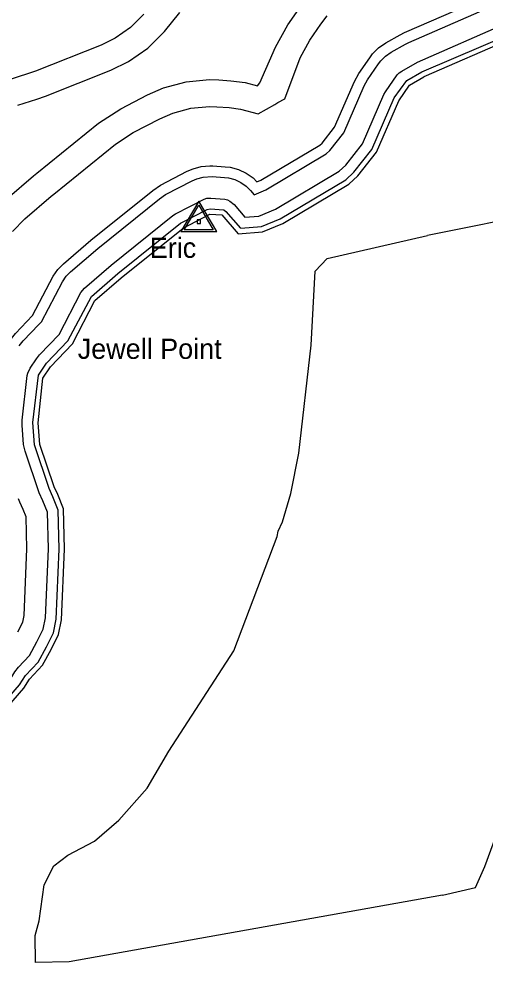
# Model space of a CAD drawing. Extents: x 2532689 to 2764727, y 536648 to 732970.
# Drawn here: x 2668083 to 2671553, y 577202 to 584335 of the extents above; entities that cross this region are included whole.
import ezdxf

# ---------------------------------------------------------------- set-up
doc = ezdxf.new("R2010")
doc.units = 0
for name, color, linetype in [('Exist Hydrographic Buffer Line', 7, 'Continuous'), ('Exist Hydrographic Creek Double Shore', 7, 'Continuous'), ('Exist Hydrographic Creek Single Shore', 7, 'Continuous'), ('Exist Hydrographic Point Label', 7, 'Continuous'), ('Exist Survey Geodetic Marker CELL', 7, 'Continuous'), ('Exist Survey Geodetic Marker Label', 7, 'Continuous')]:
    doc.layers.add(name, color=color, linetype=linetype)

msp = doc.modelspace()

# ---------------------------------------------------------------- linework, layer by layer
at = {"layer": 'Exist Hydrographic Buffer Line'}
for points in [[(2669075.8, 583062.5), (2669135.1, 583101.4), (2669333.4, 583204.6), (2669376.2, 583223.6), (2669437.1, 583239.8), (2669499.7, 583245.4), (2669523.9, 583244.6), (2669614.9, 583238.4), (2669653, 583233.7), (2669713.7, 583217.5), (2669770.5, 583191), (2669822, 583155), (2669851.5, 583125.8), (2669881.1, 583138.1), (2670318.4, 583397.5), (2670335.3, 583413.4), (2670427.9, 583531.7), (2670575.6, 583870.7), (2670608.6, 583930.4), (2670689.6, 584048.6), (2670710.9, 584076.5), (2670755, 584120.8), (2670809.3, 584158.4), (2670916.4, 584219), (2670949.4, 584235.5), (2671609.2, 584524.3)], [(2670674.6, 583885.2), (2670755.6, 584003.4), (2670772, 584025.1), (2670806.7, 584059.6), (2670848.5, 584088.8), (2670955.5, 584149.4), (2670981.4, 584162.2), (2671657.8, 584457.6)], [(2669009.2, 584372.1), (2668910.8, 584273.6), (2668796.5, 584193.6), (2668691.6, 584142.8), (2668203.5, 583949.1), (2668153.1, 583930.9), (2667984.5, 583876.8), (2667818.4, 583762.5), (2667764.5, 583728.3), (2667638, 583669.4), (2667519.1, 583637.4), (2667481.1, 583491.4), (2667422.3, 583365.1), (2667342.3, 583250.8), (2667301.5, 583210), (2667309.3, 583102.1), (2667311.6, 583043.8), (2667299.3, 582904.9), (2667259.3, 582759.1), (2667212.3, 582635.7)], [(2667994, 583001.2), (2668190, 583170), (2668215, 583191), (2668673.9, 583560.8), (2668839.2, 583669), (2669037.3, 583772.2), (2669157.4, 583825), (2669325.8, 583870.2), (2669499.5, 583885.3), (2669566.7, 583883.1), (2669657.8, 583877), (2669764.4, 583864.1), (2669854.4, 583839.9), (2669873.5, 583862), (2669988.7, 584126.3), (2670080.8, 584292.2), (2670161.8, 584410.4)], [(2668033.7, 582757.7), (2668124.6, 582849.7), (2668320.6, 583018.5), (2668340.5, 583035.3), (2668799.6, 583405.1), (2668931.9, 583491.6), (2669129.8, 583594.8), (2669226.1, 583637.1), (2669360.6, 583673.2), (2669499.5, 583685.4), (2669553.4, 583683.5), (2669644.2, 583677.4), (2669729.5, 583667.1), (2669860.1, 583632.1), (2669983.6, 583701.7), (2670007.6, 583715.3), (2670057.4, 583743.2), (2670172, 584046.5), (2670245.6, 584179.1), (2670326.6, 584297.3), (2670373.8, 584359.3)], [(2668073.5, 583695.4), (2668214, 583740.5), (2668277.6, 583763.2), (2668765.6, 583957), (2668896.6, 584020.4), (2669039.3, 584120.3), (2669162.6, 584243.6), (2669277, 584384.1)], [(2669762.1, 582863.9), (2669865.3, 582871.7), (2669988.9, 582922.9), (2670463.2, 583204.4), (2670512.8, 583250.8), (2670635.7, 583407.8), (2670795.6, 583774.8), (2670806.7, 583794.7), (2670894.6, 583922.2), (2670909.4, 583937), (2670927.6, 583949.5), (2671045.6, 584015.6), (2671712.6, 584307.3)], [(2669731.9, 582781.3), (2669884.1, 582792.9), (2670024.6, 582851.3), (2670511.4, 583140), (2670572.1, 583196.6), (2670705, 583366.5), (2670872.7, 583749.6), (2670966.8, 583879.9), (2671077.5, 583942.3), (2671756.1, 584234.5)], [(2670394.3, 583359.2), (2670497, 583490.4), (2670648.8, 583838.7), (2670674.6, 583885.2)], [(2668228.2, 582064.8), (2668248.6, 582086.2), (2668404.1, 582383.5), (2668432, 582423.5), (2668463.7, 582455.7), (2668666.7, 582630.4), (2669125.9, 583000.2), (2669172, 583030.5), (2669370.1, 583133.7), (2669403.9, 583148.5), (2669451.1, 583161.1), (2669518.3, 583164.7), (2669609.4, 583158.6), (2669639.1, 583155), (2669686.3, 583142.3), (2669730.6, 583121.7), (2669770.5, 583093.7), (2669802.7, 583061.8), (2669829.8, 583030.3), (2669916.7, 583066.4), (2670366.6, 583333.1), (2670394.3, 583359.2)], [(2667895.7, 581056.9), (2667877.5, 581146.1), (2667865.6, 581306.5), (2667866.6, 581371), (2667901.5, 581704.1), (2667905, 581728.9), (2667921.4, 581789.6), (2667947.8, 581846.4), (2667959.5, 581865.6), (2668015.5, 581949.9), (2668055.1, 581999.3), (2668183, 582133.2), (2668334.8, 582423.5), (2668370.9, 582474.9), (2668411.5, 582516.3), (2668616.7, 582692.6), (2669075.8, 583062.5)], [(2668380.1, 581992), (2668542.5, 582303.5), (2668568.3, 582334.4), (2668767.2, 582505.8), (2669226.3, 582875.6), (2669246, 582888.6), (2669458.7, 582998.1), (2669478.7, 583003.5), (2669507.7, 583005.1), (2669611.4, 582997.4), (2669631.5, 582992), (2669650.6, 582983.2), (2669681.5, 582957.4), (2669762.1, 582863.9)], [(2668305.9, 580845.9), (2668196.6, 581170), (2668184.9, 581337.6), (2668226.3, 581688.6), (2668286.6, 581778.4), (2668445.9, 581945), (2668620.6, 582273.8), (2668817.5, 582443.5), (2669283.1, 582817.6), (2669481, 582920.8), (2669502.3, 582925.3), (2669604.2, 582916.8), (2669620.9, 582905.3), (2669727.9, 582781)], [(2668082.3, 581905.7), (2668113.1, 581944.1), (2668228.2, 582064.8)], [(2668232.4, 580813.7), (2668126.3, 581124.9), (2668116.1, 581174.3), (2668105.5, 581317.4), (2668106, 581353.1), (2668141.5, 581685.2), (2668146.8, 581704.5), (2668165.1, 581740.8), (2668211.7, 581811.2), (2668233.7, 581838.6), (2668380.1, 581992)], [(2666818.4, 577463.7), (2666823.5, 577816), (2666825.9, 577840.9), (2666831.3, 577860.6), (2666846, 577891.2), (2666965.4, 578084.7), (2667059.7, 578310.9), (2667093.5, 578365), (2668021.2, 579433), (2668050.9, 579483.1), (2668078.3, 579519), (2668159.2, 579603.7), (2668214.3, 579705.5), (2668262.1, 579799.6), (2668279.3, 579883.8), (2668300.5, 580396.8), (2668294.2, 580669.1), (2668259.4, 580753.4), (2668232.4, 580813.7)], [(2667052.8, 577186.2), (2666929.3, 577446.9), (2666900.6, 577604.7), (2666903.5, 577821.5), (2666909.7, 577842), (2667036.8, 578048.1), (2667145.3, 578303.1), (2668086, 579385.8), (2668129.5, 579457.3), (2668224, 579555.9), (2668285.1, 579668.2), (2668338.5, 579773.5), (2668358.8, 579874.3), (2668380.7, 580396.1), (2668373.9, 580685.8), (2668332.9, 580785), (2668305.9, 580845.9)], [(2668072.5, 579779.8), (2668109.6, 579852.8), (2668119.9, 579903.2), (2668140.4, 580398.2), (2668134.8, 580635.5), (2668112.3, 580690.1), (2668088.1, 580744.3), (2668078.7, 580768.6)]]:
    msp.add_lwpolyline(points, dxfattribs=at)
at = {"layer": 'Exist Hydrographic Creek Double Shore'}
for points in [[(2671799.9, 584191.7), (2671753.6, 584194.5), (2671093.5, 583905.7)], [(2667175.6, 578276.9), (2668118.6, 579362.4), (2668158.6, 579429.7), (2668256.6, 579532.1), (2668320.6, 579649.6), (2668376.6, 579760.3), (2668398.5, 579869.5), (2668420.7, 580395.7), (2668413.5, 580694.2), (2668369.6, 580800.8), (2668343.6, 580858.8), (2668236.5, 581173), (2668224.7, 581333.4), (2668259.5, 581666.4), (2668315.5, 581750.8), (2668478.5, 581921.5), (2668646.6, 582243.5), (2668842.5, 582412.3), (2669301.6, 582782.2), (2669499.7, 582885.4), (2669590.5, 582879.3), (2669710.7, 582739.6), (2669893.6, 582753.6), (2670042.6, 582815.4), (2670535.6, 583107.8), (2670601.6, 583169.6), (2670739.6, 583345.9), (2670905.7, 583726.9), (2670986.7, 583845.1), (2671093.5, 583905.7)]]:
    msp.add_lwpolyline(points, dxfattribs=at)
at = {"layer": 'Exist Hydrographic Creek Single Shore'}
for points in [[(2675576.6, 579282.5), (2675524.7, 579388.7), (2675438.6, 579503.5), (2675453.8, 579563.2), (2676239.7, 580524.1), (2676230.7, 580579.5), (2676161.6, 580672), (2676134.5, 580730), (2675997.6, 580901.8), (2675463.6, 581664.9), (2675195.6, 581706.7), (2673498.6, 581917.3), (2673207.6, 581876), (2673035.6, 581757.5), (2672929.6, 581661.2), (2672829.7, 581650.6), (2672103.6, 581677.1), (2671993.7, 581741.7), (2671974.6, 581849.3), (2671967.7, 582157.6), (2672000.7, 582507), (2671983.7, 582900.3), (2671120.4, 582727.7)], [(2669034.6, 578618), (2669195.6, 578893.7), (2669679.7, 579638.8), (2670002.7, 580489.1), (2670009.6, 580528.8), (2670041.6, 580599.1), (2670103.7, 580808.4), (2670163.6, 581109.7), (2670254.7, 581911.2), (2670283.6, 582460.7), (2670373.6, 582556.2), (2671120.4, 582727.7)], [(2671231.7, 577823.5), (2668454.7, 577327.1), (2668204.8, 577323.6), (2668200.7, 577523.8), (2668231.6, 577633.3), (2668267.7, 577900.7), (2668339.7, 578041.5), (2668445.7, 578121.3), (2668643.6, 578224.6), (2668823.6, 578379.6), (2669034.6, 578618)], [(2671231.7, 577823.5), (2671475.8, 577879.3), (2671546.7, 578036.4), (2671680.8, 578399.7)]]:
    msp.add_lwpolyline(points, dxfattribs=at)
at = {"layer": 'Exist Survey Geodetic Marker CELL'}
for points in [[(2669552, 582757.2), (2669418, 582983.2), (2669284.6, 582757.2)], [(2669526.1, 582769.3), (2669310.5, 582769.3), (2669418, 582951.4)], [(2669430.3, 582815.9), (2669430.3, 582844.1), (2669406.1, 582844.1), (2669406.1, 582815.9)]]:
    msp.add_lwpolyline(points, close=True, dxfattribs=at)

# ---------------------------------------------------------------- texts
at = {"layer": 'Exist Hydrographic Point Label'}
msp.add_text('Jewell Point', height=150, dxfattribs=at).set_placement((2668518.4, 581809.7))
at = {"layer": 'Exist Survey Geodetic Marker Label'}
msp.add_text('Eric', height=150, dxfattribs=at).set_placement((2669054, 582560.6))

doc.saveas('drawing.dxf')
